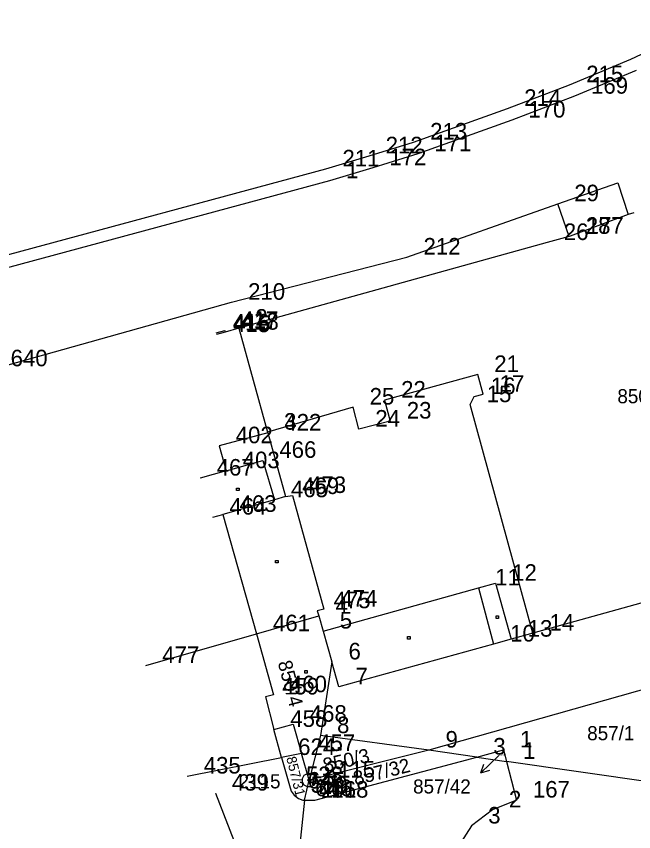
# Model space of a CAD drawing. Extents: x -822293 to -820259, y -1071573 to -1068794.
# Drawn here: x -822107.8 to -822033.4, y -1070089.8 to -1069991.4 of the extents above; entities that cross this region are included whole.
import ezdxf

# ---------------------------------------------------------------- set-up
doc = ezdxf.new("R2010")
doc.units = 0
for name, color, linetype in [('Vrstva 11', 7, 'Continuous'), ('Vrstva 14', 7, 'Continuous'), ('Vrstva 16', 7, 'Continuous'), ('Vrstva 2', 7, 'Continuous'), ('Vrstva 3', 7, 'Continuous'), ('Vrstva 5', 7, 'Continuous'), ('Vrstva 6', 7, 'Continuous'), ('Vrstva 7', 7, 'Continuous'), ('Vrstva 8', 7, 'Continuous'), ('Vrstva 9', 7, 'Continuous')]:
    doc.layers.add(name, color=color, linetype=linetype)

# ---------------------------------------------------------------- blocks, each defined once
blk = doc.blocks.new('Z61')
at = {"layer": 'Vrstva 2'}
for p, q in [((0, 300), (-50, 200)), ((0, 0), (0, 300)), ((0, 300), (50, 200))]:
    blk.add_line(p, q, dxfattribs=at)
blk = doc.blocks.new('Z402')
at = {"layer": 'Vrstva 2'}
for p, q in [((-10, 10), (20, 10)), ((-10, -20), (-10, 10)), ((20, 10), (20, -20)), ((20, -20), (-10, -20))]:
    blk.add_line(p, q, dxfattribs=at)
blk = doc.blocks.new('Z101')
at = {"layer": 'Vrstva 2'}
for p, q in [((-80, 20), (-60, 60)), ((-80, -20), (-80, 20)), ((-60, 60), (-20, 80)), ((-20, 80), (20, 80)), ((0, 0), (0, 0)), ((20, 80), (60, 60)), ((60, 60), (80, 20)), ((80, 20), (80, -20)), ((-60, -60), (-80, -20)), ((-20, -80), (-60, -60)), ((20, -80), (-20, -80)), ((60, -60), (20, -80)), ((80, -20), (60, -60))]:
    blk.add_line(p, q, dxfattribs=at)

msp = doc.modelspace()

# ---------------------------------------------------------------- linework, layer by layer
at = {"layer": 'Vrstva 2'}
for p, q in [((-822033.1, -1069997.98), (-822040.53, -1070001.08)), ((-822040.53, -1070001.08), (-822048.08, -1070003.96)), ((-822048.08, -1070003.96), (-822059.42, -1070008.02)), ((-822059.42, -1070008.02), (-822064.86, -1070009.72)), ((-822064.86, -1070009.72), (-822070.07, -1070011.29)), ((-822070.07, -1070011.29), (-822122.56, -1070025.48)), ((-822034.04, -1070015.38), (-822041.06, -1070017.97)), ((-822033.36, -1070015.15), (-822034.04, -1070015.38)), ((-822043.81, -1070018.74), (-822081.02, -1070029.08)), ((-822041.16, -1070018), (-822043.81, -1070018.74)), ((-822041.06, -1070017.97), (-822041.16, -1070018)), ((-822082.65, -1070029.56), (-822083.69, -1070029.86)), ((-822081.02, -1070029.08), (-822082.65, -1070029.56)), ((-822081.02, -1070029.08), (-822077.55, -1070041.63)), ((-822077.55, -1070041.63), (-822077.52, -1070041.73)), ((-822077.52, -1070041.73), (-822075.37, -1070049.4)), ((-822075.37, -1070049.4), (-822076.72, -1070049.78)), ((-822076.72, -1070049.78), (-822082.92, -1070051.55)), ((-822084.14, -1070051.88), (-822082.92, -1070051.55)), ((-822082.92, -1070051.55), (-822078.89, -1070065.96)), ((-822078.89, -1070065.96), (-822071.34, -1070063.8)), ((-822071.34, -1070063.8), (-822070.83, -1070065.63)), ((-822092.24, -1070069.79), (-822078.89, -1070065.96)), ((-822078.89, -1070065.96), (-822076.84, -1070073.32)), ((-822070.83, -1070065.63), (-822069.78, -1070069.36)), ((-822069.78, -1070069.36), (-822071.16, -1070078.25)), ((-822030.92, -1070072.31), (-822058.08, -1070080)), ((-822076.84, -1070073.32), (-822077.8, -1070073.59)), ((-822077.8, -1070073.59), (-822076.8, -1070077.5)), ((-822076.8, -1070077.5), (-822074.45, -1070076.88)), ((-822074.45, -1070076.88), (-822073.43, -1070080.41)), ((-822071.16, -1070078.25), (-822072.53, -1070083.62)), ((-822058.08, -1070080), (-822071.16, -1070078.25)), ((-822087.24, -1070083.13), (-822075.85, -1070080.89)), ((-822073.43, -1070080.41), (-822075.85, -1070080.89)), ((-822075.85, -1070080.89), (-822074.9, -1070084.28)), ((-822072.53, -1070083.62), (-822073.43, -1070080.41)), ((-822058.08, -1070080), (-822072.53, -1070083.62)), ((-822071.84, -1070086.04), (-822052.32, -1070080.84)), ((-822052.32, -1070080.84), (-822058.08, -1070080)), ((-822052.32, -1070080.84), (-822049.1, -1070079.98)), ((-822052.32, -1070080.84), (-822048.74, -1070081.36)), ((-822049.1, -1070079.98), (-822048.74, -1070081.36)), ((-822029.51, -1070084.15), (-822048.74, -1070081.36)), ((-822048.74, -1070081.36), (-822047.54, -1070086.03)), ((-822073.07, -1070086.04), (-822072.53, -1070083.62)), ((-822074.9, -1070084.28), (-822074.7, -1070084.95)), ((-822083.84, -1070085.19), (-822080.91, -1070092.69)), ((-822074.7, -1070084.95), (-822074.34, -1070085.45)), ((-822074.34, -1070085.45), (-822073.81, -1070085.86)), ((-822073.07, -1070086.04), (-822074.85, -1070102.22)), ((-822073.81, -1070085.86), (-822073.3, -1070086.04)), ((-822073.3, -1070086.04), (-822073.07, -1070086.04)), ((-822073.07, -1070086.04), (-822071.84, -1070086.04)), ((-822047.54, -1070086.03), (-822050.43, -1070087.21)), ((-822050.43, -1070087.21), (-822052.93, -1070089.16)), ((-822052.93, -1070089.16), (-822054.91, -1070092.21))]:
    msp.add_line(p, q, dxfattribs=at)
at = {"layer": 'Vrstva 3'}
for p, q in [((-822033.75, -1069996.63), (-822022.9, -1069991.44)), ((-822041.11, -1069999.7), (-822033.75, -1069996.63)), ((-822048.59, -1070002.55), (-822041.11, -1069999.7)), ((-822059.93, -1070006.61), (-822048.59, -1070002.55)), ((-822065.3, -1070008.28), (-822059.93, -1070006.61)), ((-822070.51, -1070009.86), (-822065.3, -1070008.28)), ((-822122.99, -1070024.04), (-822070.51, -1070009.86)), ((-822042.55, -1070014.06), (-822035.28, -1070011.52)), ((-822035.28, -1070011.52), (-822034.04, -1070015.38)), ((-822060.73, -1070020.49), (-822042.55, -1070014.06)), ((-822041.16, -1070018), (-822042.55, -1070014.06)), ((-822081.89, -1070025.95), (-822060.73, -1070020.49)), ((-822110.53, -1070033.98), (-822081.89, -1070025.95)), ((-822083.74, -1070029.66), (-822082.71, -1070029.36)), ((-822082.71, -1070029.36), (-822082.65, -1070029.56)), ((-822052.2, -1070034.67), (-822063.43, -1070037.76)), ((-822051.55, -1070037.06), (-822052.2, -1070034.67)), ((-822053.11, -1070038.31), (-822052.61, -1070037.34)), ((-822052.61, -1070037.34), (-822051.55, -1070037.06)), ((-822067.23, -1070038.6), (-822077.55, -1070041.63)), ((-822066.55, -1070041.26), (-822067.23, -1070038.6)), ((-822063.43, -1070037.76), (-822062.75, -1070040.29)), ((-822045.54, -1070065.88), (-822053.11, -1070038.31)), ((-822062.75, -1070040.29), (-822066.55, -1070041.26)), ((-822077.52, -1070041.73), (-822083.38, -1070043.27)), ((-822083.38, -1070043.27), (-822082.54, -1070046.28)), ((-822082.54, -1070046.28), (-822078.12, -1070045.03)), ((-822078.12, -1070045.03), (-822076.72, -1070049.78)), ((-822082.54, -1070046.28), (-822085.68, -1070047.17)), ((-822075.37, -1070049.4), (-822074.53, -1070049.27)), ((-822074.53, -1070049.27), (-822070.77, -1070062.99)), ((-822052.09, -1070060.43), (-822050.04, -1070059.87)), ((-822050.04, -1070059.87), (-822048.17, -1070066.61)), ((-822070.83, -1070065.63), (-822052.09, -1070060.43)), ((-822052.09, -1070060.43), (-822050.28, -1070067.2)), ((-822030.97, -1070061.85), (-822045.54, -1070065.88)), ((-822070.77, -1070062.99), (-822071.58, -1070063.18)), ((-822071.58, -1070063.18), (-822071.34, -1070063.8)), ((-822045.54, -1070065.88), (-822048.17, -1070066.61)), ((-822048.17, -1070066.61), (-822050.28, -1070067.2)), ((-822050.28, -1070067.2), (-822068.93, -1070072.36)), ((-822068.93, -1070072.36), (-822069.78, -1070069.36)), ((-822075.85, -1070080.89), (-822076.8, -1070077.5))]:
    msp.add_line(p, q, dxfattribs=at)
at = {"layer": 'Vrstva 8'}
for p, q in [((-822033.75, -1069996.63), (-822033.75, -1069996.63)), ((-822041.11, -1069999.7), (-822041.11, -1069999.7)), ((-822040.53, -1070001.08), (-822040.53, -1070001.08)), ((-822048.59, -1070002.55), (-822048.59, -1070002.55)), ((-822048.08, -1070003.96), (-822048.08, -1070003.96)), ((-822059.93, -1070006.61), (-822059.93, -1070006.61)), ((-822059.42, -1070008.02), (-822059.42, -1070008.02)), ((-822065.3, -1070008.28), (-822065.3, -1070008.28)), ((-822070.51, -1070009.86), (-822070.51, -1070009.86)), ((-822064.86, -1070009.72), (-822064.86, -1070009.72)), ((-822070.07, -1070011.29), (-822070.07, -1070011.29)), ((-822035.28, -1070011.52), (-822035.28, -1070011.52)), ((-822042.55, -1070014.06), (-822042.55, -1070014.06)), ((-822034.04, -1070015.38), (-822034.04, -1070015.38)), ((-822043.81, -1070018.74), (-822043.81, -1070018.74)), ((-822041.16, -1070018), (-822041.16, -1070018)), ((-822041.06, -1070017.97), (-822041.06, -1070017.97)), ((-822060.73, -1070020.49), (-822060.73, -1070020.49)), ((-822081.89, -1070025.95), (-822081.89, -1070025.95)), ((-822083.74, -1070029.66), (-822083.74, -1070029.66)), ((-822082.71, -1070029.36), (-822082.71, -1070029.36)), ((-822082.65, -1070029.56), (-822082.65, -1070029.56)), ((-822081.02, -1070029.08), (-822081.02, -1070029.08)), ((-822083.69, -1070029.86), (-822083.69, -1070029.86)), ((-822052.2, -1070034.67), (-822052.2, -1070034.67)), ((-822052.61, -1070037.34), (-822052.61, -1070037.34)), ((-822051.55, -1070037.06), (-822051.55, -1070037.06)), ((-822067.23, -1070038.6), (-822067.23, -1070038.6)), ((-822063.43, -1070037.76), (-822063.43, -1070037.76)), ((-822053.11, -1070038.31), (-822053.11, -1070038.31)), ((-822062.75, -1070040.29), (-822062.75, -1070040.29)), ((-822066.55, -1070041.26), (-822066.55, -1070041.26)), ((-822077.55, -1070041.63), (-822077.55, -1070041.63)), ((-822077.52, -1070041.73), (-822077.52, -1070041.73)), ((-822083.38, -1070043.27), (-822083.38, -1070043.27)), ((-822078.12, -1070045.03), (-822078.12, -1070045.03)), ((-822082.54, -1070046.28), (-822082.54, -1070046.28)), ((-822085.68, -1070047.17), (-822085.68, -1070047.17)), ((-822075.37, -1070049.4), (-822075.37, -1070049.4)), ((-822074.53, -1070049.27), (-822074.53, -1070049.27)), ((-822076.72, -1070049.78), (-822076.72, -1070049.78)), ((-822084.14, -1070051.88), (-822084.14, -1070051.88)), ((-822082.92, -1070051.55), (-822082.92, -1070051.55)), ((-822050.04, -1070059.87), (-822050.04, -1070059.87)), ((-822052.09, -1070060.43), (-822052.09, -1070060.43)), ((-822071.58, -1070063.18), (-822071.58, -1070063.18)), ((-822070.77, -1070062.99), (-822070.77, -1070062.99)), ((-822071.34, -1070063.8), (-822071.34, -1070063.8)), ((-822078.89, -1070065.96), (-822078.89, -1070065.96)), ((-822070.83, -1070065.63), (-822070.83, -1070065.63)), ((-822045.54, -1070065.88), (-822045.54, -1070065.88)), ((-822048.17, -1070066.61), (-822048.17, -1070066.61)), ((-822050.28, -1070067.2), (-822050.28, -1070067.2)), ((-822092.24, -1070069.79), (-822092.24, -1070069.79)), ((-822069.78, -1070069.36), (-822069.78, -1070069.36)), ((-822068.93, -1070072.36), (-822068.93, -1070072.36)), ((-822077.8, -1070073.59), (-822077.8, -1070073.59)), ((-822076.84, -1070073.32), (-822076.84, -1070073.32)), ((-822074.45, -1070076.88), (-822074.45, -1070076.88)), ((-822076.8, -1070077.5), (-822076.8, -1070077.5)), ((-822071.16, -1070078.25), (-822071.16, -1070078.25)), ((-822075.85, -1070080.89), (-822075.85, -1070080.89)), ((-822073.43, -1070080.41), (-822073.43, -1070080.41)), ((-822058.08, -1070080), (-822058.08, -1070080)), ((-822052.32, -1070080.84), (-822052.32, -1070080.84)), ((-822049.1, -1070079.98), (-822049.1, -1070079.98)), ((-822048.74, -1070081.36), (-822048.74, -1070081.36)), ((-822087.24, -1070083.13), (-822087.24, -1070083.13)), ((-822072.53, -1070083.62), (-822072.53, -1070083.62)), ((-822074.9, -1070084.28), (-822074.9, -1070084.28)), ((-822083.84, -1070085.19), (-822083.84, -1070085.19)), ((-822074.7, -1070084.95), (-822074.7, -1070084.95)), ((-822074.34, -1070085.45), (-822074.34, -1070085.45)), ((-822073.81, -1070085.86), (-822073.81, -1070085.86)), ((-822073.3, -1070086.04), (-822073.3, -1070086.04)), ((-822073.07, -1070086.04), (-822073.07, -1070086.04)), ((-822071.84, -1070086.04), (-822071.84, -1070086.04)), ((-822047.54, -1070086.03), (-822047.54, -1070086.03)), ((-822050.43, -1070087.21), (-822050.43, -1070087.21)), ((-822052.93, -1070089.16), (-822052.93, -1070089.16))]:
    msp.add_line(p, q, dxfattribs=at)

# ---------------------------------------------------------------- block references
at = {"layer": 'Vrstva 11', "xscale": 0.01, "yscale": 0.01}
for p in [(-822081.18, -1070048.47), (-822076.48, -1070057.2), (-822049.89, -1070063.9), (-822060.55, -1070066.41), (-822072.95, -1070070.51), (-822068.9, -1070079.79)]:
    msp.add_blockref('Z402', p, dxfattribs=at)
at = {"layer": 'Vrstva 14', "xscale": 0.01, "yscale": 0.01}
msp.add_blockref('Z101', (-822072.53, -1070083.62), dxfattribs=at)
at = {"layer": 'Vrstva 7', "xscale": 0.01, "yscale": 0.010000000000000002, "rotation": 134.0000000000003}
msp.add_blockref('Z61', (-822049.66, -1070080.67), dxfattribs=at)

# ---------------------------------------------------------------- texts
at = {"layer": 'Vrstva 16'}
msp.add_text('2115', height=1.7, dxfattribs=at).set_placement((-822081.04, -1070084.62))
at = {"layer": 'Vrstva 5'}
for s, height, p in [('857/1', 1.7, (-822038.993, -1070078.81)), ('857/42', 0.2, (-822049.66, -1070080.67))]:
    msp.add_text(s, height=height, dxfattribs=at).set_placement(p)
for s, height, rotation, p in [('857/31', 1.199, 284, (-822075.3, -1070080.93)), ('857/32', 1.7, 14, (-822066.955, -1070084.278))]:
    msp.add_text(s, height=height, rotation=rotation, dxfattribs=at).set_placement(p)
at = {"layer": 'Vrstva 6'}
msp.add_text('850/1', height=1.7, dxfattribs=at).set_placement((-822035.353, -1070038.14))
for s, rotation, p in [('850/4', 285, (-822076.33, -1070069.43)), ('850/3', 13, (-822070.64, -1070082.7))]:
    msp.add_text(s, height=1.7, rotation=rotation, dxfattribs=at).set_placement(p)
at = {"layer": 'Vrstva 7'}
msp.add_text('857/42', height=1.7, dxfattribs=at).set_placement((-822059.991, -1070085.24))
at = {"layer": 'Vrstva 9'}
for s, p in [('215', (-822039.11, -1069999.4)), ('169', (-822038.53, -1070000.78)), ('214', (-822046.59, -1070002.25)), ('170', (-822046.08, -1070003.66)), ('213', (-822057.93, -1070006.31)), ('212', (-822063.3, -1070007.98)), ('171', (-822057.42, -1070007.72)), ('211', (-822068.51, -1070009.56)), ('172', (-822062.86, -1070009.42)), ('1', (-822068.07, -1070010.99)), ('29', (-822040.55, -1070013.76)), ('28', (-822039.16, -1070017.7)), ('177', (-822039.06, -1070017.67)), ('26', (-822041.81, -1070018.44)), ('212', (-822058.73, -1070020.19)), ('210', (-822079.89, -1070025.65)), ('2', (-822079.02, -1070028.78)), ('416', (-822081.74, -1070029.36)), ('415', (-822081.69, -1070029.56)), ('417', (-822080.71, -1070029.06)), ('418', (-822080.65, -1070029.26)), ('640', (-822108.53, -1070033.68)), ('21', (-822050.2, -1070034.37)), ('22', (-822061.43, -1070037.46)), ('16', (-822050.61, -1070037.04)), ('17', (-822049.55, -1070036.76)), ('25', (-822065.23, -1070038.3)), ('15', (-822051.11, -1070038.01)), ('23', (-822060.75, -1070039.99)), ('422', (-822075.52, -1070041.43)), ('3', (-822075.55, -1070041.33)), ('24', (-822064.55, -1070040.96)), ('402', (-822081.38, -1070042.97)), ('466', (-822076.12, -1070044.73)), ('403', (-822080.54, -1070045.98)), ('467', (-822083.68, -1070046.87)), ('465', (-822074.72, -1070049.48)), ('469', (-822073.37, -1070049.1)), ('473', (-822072.53, -1070048.97)), ('463', (-822080.92, -1070051.25)), ('464', (-822082.14, -1070051.58)), ('11', (-822050.09, -1070060.13)), ('12', (-822048.04, -1070059.57)), ('475', (-822069.58, -1070062.88)), ('474', (-822068.77, -1070062.69)), ('4', (-822069.34, -1070063.5)), ('461', (-822076.89, -1070065.66)), ('5', (-822068.83, -1070065.33)), ('14', (-822043.54, -1070065.58)), ('10', (-822048.28, -1070066.9)), ('13', (-822046.17, -1070066.31)), ('6', (-822067.78, -1070069.06)), ('477', (-822090.24, -1070069.49)), ('7', (-822066.93, -1070072.06)), ('460', (-822074.84, -1070073.02)), ('459', (-822075.8, -1070073.29)), ('468', (-822072.45, -1070076.58)), ('458', (-822074.8, -1070077.2)), ('8', (-822069.16, -1070077.95)), ('9', (-822056.08, -1070079.7)), ('1', (-822047.1, -1070079.68)), ('624', (-822073.85, -1070080.59)), ('457', (-822071.43, -1070080.11)), ('3', (-822050.32, -1070080.54)), ('1', (-822046.74, -1070081.06)), ('435', (-822085.24, -1070082.83)), ('2115', (-822070.53, -1070083.32)), ('439', (-822081.84, -1070084.89)), ('538', (-822072.9, -1070083.98)), ('645', (-822072.7, -1070084.65)), ('539', (-822072.34, -1070085.15)), ('646', (-822071.81, -1070085.56)), ('401', (-822071.3, -1070085.74)), ('2', (-822071.07, -1070085.74)), ('168', (-822069.84, -1070085.74)), ('167', (-822045.54, -1070085.73)), ('2', (-822048.43, -1070086.91)), ('3', (-822050.93, -1070088.86))]:
    msp.add_text(s, height=2, dxfattribs=at).set_placement(p)

doc.saveas('drawing.dxf')
